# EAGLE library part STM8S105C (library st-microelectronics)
Access line, 16 MHz STM8S 8-bit MCU up to 32 Kbytes Flash, integrated EEPROM,10-bit ADC, timers, UART, SPI, I²C Source: Data sheet
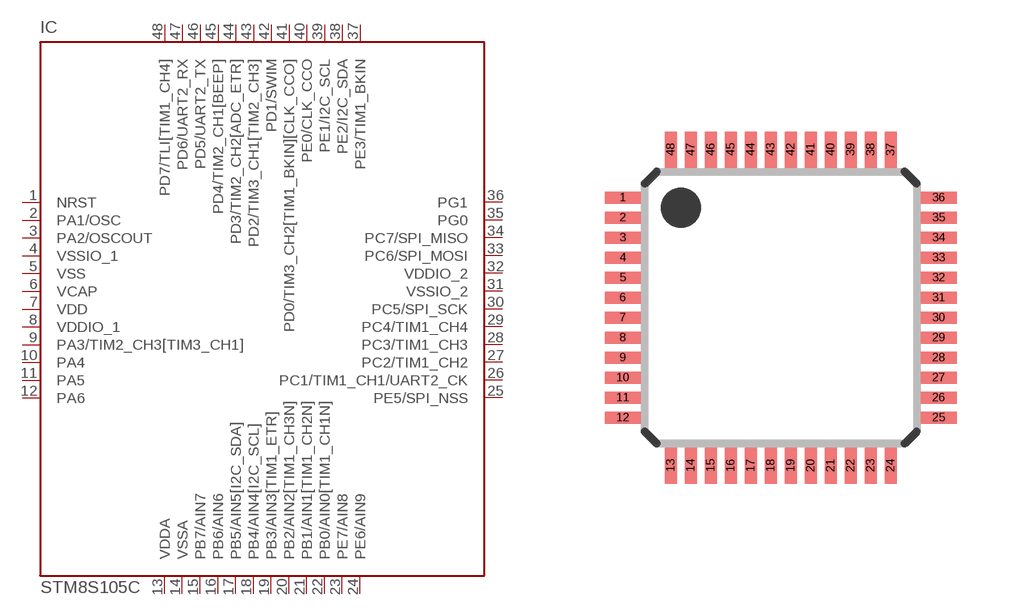
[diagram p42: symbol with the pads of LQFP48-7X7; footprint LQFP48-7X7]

Designator prefix IC

## STM8S105C4 (MPN: STM8S105C4T6; OC_FARNELL: 1706221; OC_NEWARK: 09R6031), STM8S105C6 (MPN: STM8S105C6T6; OC_FARNELL: 1706222; OC_NEWARK: 09R6033)  [LQFP48-7X7]
1  NRST
2  PA1/OSC
3  PA2/OSCOUT
4  VSSIO_1  pwr
5  VSS  pwr
6  VCAP  pwr
7  VDD  pwr
8  VDDIO_1  pwr
9  PA3/TIM2_CH3[TIM3_CH1]
10  PA4
11  PA5
12  PA6
13  VDDA  pwr
14  VSSA  pwr
15  PB7/AIN7
16  PB6/AIN6
17  PB5/AIN5[I2C_SDA]
18  PB4/AIN4[I2C_SCL]
19  PB3/AIN3[TIM1_ETR]
20  PB2/AIN2[TIM1_CH3N]
21  PB1/AIN1[TIM1_CH2N]
22  PB0/AIN0[TIM1_CH1N]
23  PE7/AIN8
24  PE6/AIN9
25  PE5/SPI_NSS
26  PC1/TIM1_CH1/UART2_CK
27  PC2/TIM1_CH2
28  PC3/TIM1_CH3
29  PC4/TIM1_CH4
30  PC5/SPI_SCK
31  VSSIO_2  pwr
32  VDDIO_2  pwr
33  PC6/SPI_MOSI
34  PC7/SPI_MISO
35  PG0
36  PG1
37  PE3/TIM1_BKIN
38  PE2/I2C_SDA
39  PE1/I2C_SCL
40  PE0/CLK_CCO
41  PD0/TIM3_CH2[TIM1_BKIN][CLK_CCO]
42  PD1/SWIM
43  PD2/TIM3_CH1[TIM2_CH3]
44  PD3/TIM2_CH2[ADC_ETR]
45  PD4/TIM2_CH1[BEEP]
46  PD5/UART2_TX
47  PD6/UART2_RX
48  PD7/TLI[TIM1_CH4]

## Footprint LQFP48-7X7 (pad centres in mm)
48-pin low profile quad flat package (7 x 7) Source: Data sheet
smd 0.9 x 0.3: 1 -3.95,2.75; 2 -3.95,2.25; 3 -3.95,1.75; 4 -3.95,1.25; 5 -3.95,0.75; 6 -3.95,0.25; 7 -3.95,-0.25; 8 -3.95,-0.75; 9 -3.95,-1.25; 10 -3.95,-1.75; 11 -3.95,-2.25; 12 -3.95,-2.75; 25 3.95,-2.75; 26 3.95,-2.25; 27 3.95,-1.75; 28 3.95,-1.25; 29 3.95,-0.75; 30 3.95,-0.25; 31 3.95,0.25; 32 3.95,0.75; 33 3.95,1.25; 34 3.95,1.75; 35 3.95,2.25; 36 3.95,2.75
smd 0.3 x 0.9: 13 -2.75,-3.95; 14 -2.25,-3.95; 15 -1.75,-3.95; 16 -1.25,-3.95; 17 -0.75,-3.95; 18 -0.25,-3.95; 19 0.25,-3.95; 20 0.75,-3.95; 21 1.25,-3.95; 22 1.75,-3.95; 23 2.25,-3.95; 24 2.75,-3.95; 37 2.75,3.95; 38 2.25,3.95; 39 1.75,3.95; 40 1.25,3.95; 41 0.75,3.95; 42 0.25,3.95; 43 -0.25,3.95; 44 -0.75,3.95; 45 -1.25,3.95; 46 -1.75,3.95; 47 -2.25,3.95; 48 -2.75,3.95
